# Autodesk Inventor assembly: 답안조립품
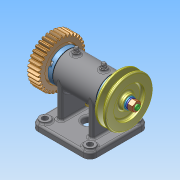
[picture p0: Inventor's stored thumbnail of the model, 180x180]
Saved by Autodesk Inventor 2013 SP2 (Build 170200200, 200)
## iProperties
Created: 2025-10
Part Number: 답안조립품
Document SubType Name: Assembly
Designer: a
Author: a
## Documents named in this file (17)
- C:\Users\a\Desktop\751003V1014\답안조립품.iam
- C:\Users\a\Desktop\751003V1014\6각 구멍붙이 볼트 M4x10.ipt
- C:\Users\a\Desktop\751003V1014\6각 너트 M8x1.ipt
- C:\Users\a\Desktop\751003V1014\6각 머리 볼트 M6x0.75x8.ipt
- C:\Users\a\Desktop\751003V1014\V 벨트 풀리.ipt
- C:\Users\a\Desktop\751003V1014\가스켓.ipt
- C:\Users\a\Desktop\751003V1014\그리스 니플 M6x0.75.ipt
- C:\Users\a\Desktop\751003V1014\깊은 홈 볼 베어링 6002.ipt
- C:\Users\a\Desktop\751003V1014\본체.ipt
- C:\Users\a\Desktop\751003V1014\스퍼 기어.ipt
- C:\Users\a\Desktop\751003V1014\스프링 와셔 M8.ipt
- C:\Users\a\Desktop\751003V1014\실링.ipt
- C:\Users\a\Desktop\751003V1014\오일 실 15 25 4.ipt
- C:\Users\a\Desktop\751003V1014\축.ipt
- C:\Users\a\Desktop\751003V1014\커버.ipt
- C:\Users\a\Desktop\751003V1014\평 와셔 M8.ipt
- C:\Users\a\Desktop\751003V1014\평행 키 3x3x12.ipt
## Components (14 placed, 6 different names)
1. 6각 너트 M8x1:1
2. 6각 머리 볼트 M6x0.75x8:1
3. V 벨트 풀리:1
4. 가스켓:1
5. 그리스 니플 M6x0.75:1
6. 가스켓:2
7. 6각 너트 M8x1:2
8. 그리스 니플 M6x0.75:2
9. 6각 구멍붙이 볼트 M4x10:1
10. 6각 구멍붙이 볼트 M4x10:3
11. 6각 구멍붙이 볼트 M4x10:4
12. 6각 구멍붙이 볼트 M4x10:2
13. 6각 구멍붙이 볼트 M4x10:5
14. 6각 구멍붙이 볼트 M4x10:6
